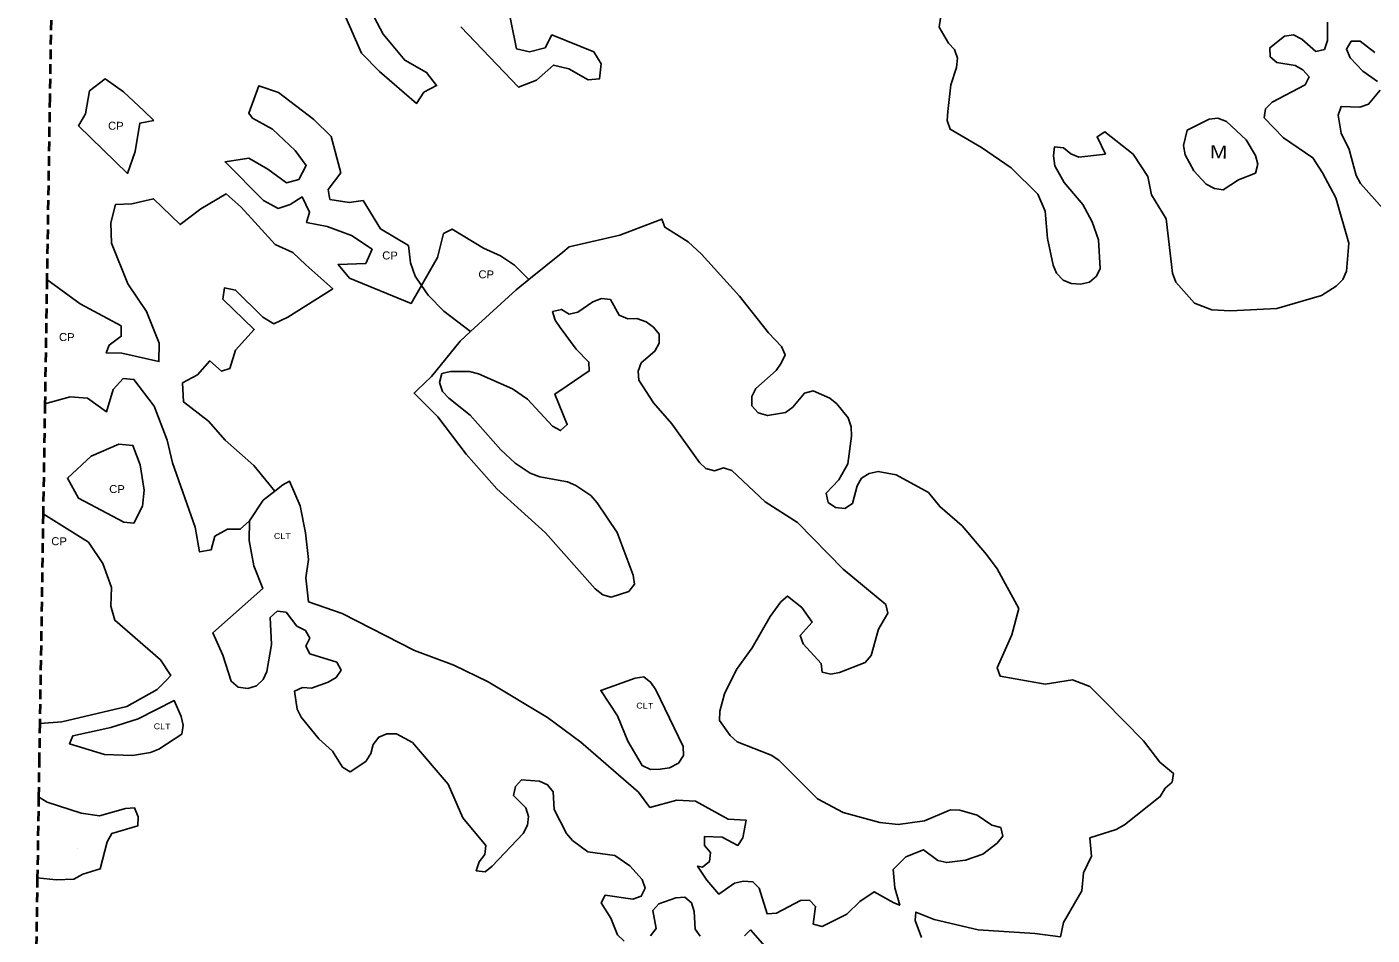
# Model space of a CAD drawing. Extents: x 713589 to 726391, y 7177764 to 7191819.
# Drawn here: x 713596 to 714671, y 7178865 to 7179591 of the extents above; entities that cross this region are included whole.
import ezdxf
from ezdxf.enums import TextEntityAlignment as Align

# ---------------------------------------------------------------- set-up
doc = ezdxf.new("R2010")
doc.units = 0
doc.header["$LTSCALE"] = 2.6
doc.linetypes.add('MEDIUM_DASHED', pattern=[4.5, 3, -1.5])
doc.layers.add('63', color=7, linetype='Continuous', lineweight=25)

msp = doc.modelspace()

# ---------------------------------------------------------------- linework, layer by layer
at = {"layer": '63', "linetype": 'MEDIUM_DASHED', "lineweight": 40}
for p, q in [((713608.65, 7179201.34), (713605.98, 7179033.91)), ((713605.04, 7178975.31), (713604, 7178910.37))]:
    msp.add_line(p, q, dxfattribs=at)
for points in [[(713619.62, 7179888.54), (713613.97, 7179534.19), (713611.65, 7179388.89)], [(713611.65, 7179388.89), (713610.06, 7179289.38), (713608.65, 7179201.34)], [(713605.98, 7179033.91), (713605.54, 7179006.32), (713605.04, 7178975.31)], [(713604, 7178910.37), (713599.18, 7178608.3), (713595.68, 7178388.53)]]:
    msp.add_lwpolyline(points, dxfattribs=at)
at = {"layer": '63'}
for points in [[(713942.56, 7179590.82), (713988.88, 7179542.69), (714003.14, 7179548.3), (714016.75, 7179560.21), (714029, 7179557.21), (714044.57, 7179548.56), (714053.52, 7179549.21), (714054.86, 7179561.14), (714048.91, 7179570.76), (714015.46, 7179584.41), (714010.14, 7179574.14), (713997.54, 7179570.85), (713987.27, 7179573.18), (713978.73, 7179615.62)], [(713848.79, 7179602.58), (713863.32, 7179569.74), (713877.55, 7179555.14), (713907.34, 7179529.57), (713912.98, 7179538.51), (713923.26, 7179543.79), (713915.33, 7179554.41), (713897.78, 7179564.05), (713880.58, 7179584.96), (713871, 7179603.2)], [(714635.66, 7179594.6), (714635.64, 7179579.8), (714633.31, 7179572.73), (714626.34, 7179570.98), (714615.2, 7179580.83), (714608.58, 7179584.37), (714601.29, 7179583.39), (714589.67, 7179574.13), (714589.77, 7179566.95), (714595.29, 7179562.41), (714609.75, 7179559.96), (714615.93, 7179556.41), (714621.01, 7179550.88), (714617.79, 7179544.48), (714591.48, 7179530.49), (714586.17, 7179525.2), (714584.94, 7179518.13), (714600.6, 7179502.2), (714624.1, 7179486.14), (714631.82, 7179474.08), (714642.39, 7179454.18), (714652.82, 7179417.82), (714650.8, 7179395.51), (714647.91, 7179388.88), (714642.71, 7179383.59), (714630.88, 7179375.99), (714595.29, 7179365.66), (714558.17, 7179363.74), (714543.15, 7179364.53), (714529.24, 7179369.86), (714514.35, 7179386.79), (714511.71, 7179393.75), (714506.59, 7179437.39), (714495.02, 7179456.53), (714492.07, 7179471.11), (714480.28, 7179489.03), (714457.66, 7179506.74), (714451.47, 7179502.88), (714458.18, 7179489.06), (714436.86, 7179486.67), (714430.34, 7179489.33), (714424.5, 7179493.98), (714417.54, 7179494.99), (714416.53, 7179487.59), (714417.62, 7179479.74), (714425.22, 7179466.36), (714440.11, 7179448.77), (714447.49, 7179434.95), (714452.54, 7179420.47), (714454.05, 7179397.71), (714450.95, 7179391.42), (714445.31, 7179386.79), (714438.12, 7179385.14), (714430.83, 7179385.6), (714424.21, 7179388.15), (714419.14, 7179393.9), (714416.28, 7179400.32), (714411.78, 7179421.64), (714409.94, 7179443.52), (714404, 7179457.12), (714382.71, 7179478.03), (714358.99, 7179494.31), (714333.93, 7179508.93), (714331.63, 7179515.9), (714332.08, 7179523.08), (714334.44, 7179544.51), (714339.1, 7179558.31), (714339.88, 7179565.71), (714337.46, 7179572.56), (714332.61, 7179577.87), (714325.12, 7179590.59), (714326.13, 7179597.77)], [(714675.68, 7179547.08), (714664.1, 7179555.49), (714653.84, 7179566.11), (714650.87, 7179572.97), (714654.75, 7179579.26), (714661.93, 7179579.25), (714673.51, 7179570.39)], [(714691.07, 7179433.05), (714662.18, 7179465.68), (714658.77, 7179471.98), (714653.17, 7179492.76), (714646.56, 7179505.81), (714644.15, 7179520.17), (714646.71, 7179527.13), (714661.62, 7179526.66), (714668.58, 7179529.08), (714677.77, 7179540.11)], [(713611.65, 7179388.89), (713638.29, 7179369.28), (713671.07, 7179351.66), (713671.06, 7179343.38), (713661.43, 7179336.43), (713659.1, 7179330.14), (713671.7, 7179329.79), (713701.18, 7179323.11), (713701.54, 7179338.02), (713691.31, 7179363.23), (713676.43, 7179385.46), (713663.23, 7179417.96), (713662.92, 7179434.2), (713666.59, 7179448.77), (713679.52, 7179449.42), (713696.97, 7179453.36), (713718.18, 7179432.7), (713734.86, 7179445.35), (713755.09, 7179457.24), (713767.01, 7179446.62), (713794.13, 7179416.75), (713808.37, 7179410.43), (713818.63, 7179400.47), (713840.21, 7179381.35), (713804.31, 7179358.73), (713793.03, 7179353.45), (713784.42, 7179358.77), (713762.59, 7179380.34), (713753.64, 7179382.02), (713752.3, 7179373.07), (713777.45, 7179348.83), (713762.51, 7179332.29), (713757.84, 7179317.71), (713751.21, 7179315.41), (713741.95, 7179323.71), (713731.99, 7179312.45), (713720.04, 7179306.18), (713721.01, 7179290.93), (713740.87, 7179275.65), (713754.1, 7179260.39), (713777.27, 7179240.13), (713794.05, 7179219.61)], [(713997.05, 7179388.81), (714024.12, 7179410.76), (714029.18, 7179414.86), (714069.88, 7179424.24), (714103.3, 7179437.07), (714105.9, 7179430.55), (714124.55, 7179418.81), (714135.25, 7179408.96), (714165.58, 7179375.54), (714188.62, 7179346.23), (714199.09, 7179335.28), (714201.95, 7179328.53), (714198.74, 7179321.91), (714194.86, 7179316.06), (714178.49, 7179301.73), (714175.28, 7179295.33), (714175.48, 7179287.81), (714180.56, 7179282.17), (714187.95, 7179280.06), (714202.21, 7179282.47), (714208.07, 7179286.65), (714217.48, 7179297.8), (714224.44, 7179299.77), (714237.69, 7179293.9), (714243.32, 7179289.36), (714252.36, 7179278.08), (714254.77, 7179271.11), (714255.2, 7179263.6), (714252.18, 7179241.51), (714244.87, 7179228.71), (714234.8, 7179217.9), (714236.45, 7179210.6), (714242.41, 7179206.62), (714249.69, 7179205.72), (714255.78, 7179209.8), (714259.67, 7179223.71), (714263.1, 7179229.89), (714269.29, 7179233.64), (714276.48, 7179235.39), (714290.83, 7179232.72), (714316.55, 7179218.43), (714325.59, 7179207.25), (714343.57, 7179191.98), (714363.09, 7179168.86), (714371.57, 7179157.46), (714388.76, 7179125.84), (714383.2, 7179104.75), (714371.66, 7179078.26), (714373.97, 7179071.62), (714409.98, 7179065.38), (714431.74, 7179068.77), (714445.65, 7179063.44), (714457.24, 7179052.04), (714488.45, 7179019.85), (714501.56, 7179003.03), (714512.48, 7178993.96), (714511.48, 7178987), (714505.84, 7178982.04), (714501.96, 7178975.41), (714473.31, 7178952.81), (714466.68, 7178949.07), (714445.68, 7178942.37), (714446.98, 7178927.78), (714440.55, 7178914.31), (714439.2, 7178900.07), (714424.68, 7178874.79), (714422.19, 7178863.19), (714401.58, 7178865.9), (714356.38, 7178868.76), (714321.07, 7178876.98), (714306.62, 7178883.02), (714306.04, 7178876.31), (714311.1, 7178862.72)], [(713997.05, 7179388.81), (713985.66, 7179400.19), (713974.41, 7179407.83), (713960.83, 7179413.82), (713935.67, 7179429.11), (713928.7, 7179425.47), (713924.03, 7179406.26), (713911.25, 7179384.07)], [(713911.25, 7179384.07), (713916.54, 7179376.32), (713929.14, 7179363.52), (713950.4, 7179347.17)], [(713997.05, 7179388.81), (713986.95, 7179380.63), (713950.4, 7179347.17)], [(714212.01, 7179194.41), (714186.07, 7179210.91), (714159.49, 7179236.03), (714152.76, 7179238.14), (714145.57, 7179235.83), (714138.72, 7179237.61), (714133.65, 7179242.59), (714111.28, 7179273.45), (714096.72, 7179290.26), (714084.93, 7179308.4), (714084.39, 7179315.58), (714086.94, 7179322.1), (714097.79, 7179331.58), (714101.22, 7179337.87), (714101.34, 7179345.05), (714096.82, 7179350.69), (714090.86, 7179355.01), (714083.36, 7179357.56), (714076.29, 7179357.35), (714069.22, 7179360.24), (714062.28, 7179372.84), (714055.21, 7179373.74), (714048.25, 7179370.99), (714036.3, 7179362.61), (714029.23, 7179360.97), (714023.16, 7179364.84), (714016.09, 7179363.2), (714018.07, 7179356.24), (714022.14, 7179350.37), (714034.82, 7179333.12), (714045.08, 7179322.72), (714045.4, 7179315.65), (714027.82, 7179303.84), (714017.93, 7179297.2), (714027.76, 7179272.81), (714022.45, 7179267.96), (714016.05, 7179271.62), (713995.87, 7179293.19), (713984.06, 7179301.5), (713956.79, 7179313.25), (713949.73, 7179315.36), (713934.37, 7179315.17), (713927.52, 7179313.52), (713925.63, 7179306.35), (713928.05, 7179299.27), (713933.01, 7179293.96), (713950.11, 7179280.23), (713974.7, 7179252.69), (713986.17, 7179242.06), (713998.2, 7179233.98), (714005.93, 7179231.09), (714027.9, 7179226.97), (714034.64, 7179223.97), (714046.67, 7179216), (714051.63, 7179210.36), (714067.72, 7179186.47), (714080.48, 7179152.42), (714081.46, 7179145.24), (714076.92, 7179139.39), (714062.99, 7179134.89), (714056.15, 7179136.78), (714050.19, 7179141.54), (714010.38, 7179186.23), (713971.45, 7179221.54), (713946.97, 7179249.09), (713924.37, 7179279.06), (713905.32, 7179298.03), (713907.9, 7179300.47), (713919.23, 7179311.15), (713942.15, 7179339.61), (713950.4, 7179347.17)], [(713773.55, 7179195.73), (713766.25, 7179189.11), (713755.97, 7179189.13), (713746.02, 7179183.51), (713743.02, 7179172.58), (713733.74, 7179170.94), (713730.13, 7179190.83), (713711.98, 7179242.23), (713707.71, 7179260.46), (713697.48, 7179287.66), (713681.27, 7179308.89), (713672.66, 7179309.57), (713664.69, 7179300.97), (713659.36, 7179283.08), (713644.13, 7179294.04), (713630.21, 7179295.06), (713610.06, 7179289.38)], [(713794.05, 7179219.61), (713800.44, 7179224.52), (713805.7, 7179227.47), (713814.11, 7179207.88), (713818.5, 7179186.33), (713820.78, 7179164.9), (713818.66, 7179150.32), (713820.91, 7179131.06), (713847.66, 7179121.7), (713905.61, 7179092.11), (713937.08, 7179080.46), (713964.56, 7179067.16), (714011.91, 7179038.58), (714038.72, 7179018.98), (714084.72, 7178978.8), (714093.88, 7178966.67), (714115.42, 7178972.41), (714130.22, 7178971.61), (714156.38, 7178957.21), (714170.85, 7178956.41), (714168.28, 7178942.27), (714164.08, 7178936.31), (714151.6, 7178942.96), (714137.46, 7178943.43), (714137.45, 7178936.14), (714142.3, 7178930.61), (714141.52, 7178923.43), (714135.99, 7178918.91), (714132.02, 7178919.84), (714139.28, 7178908.45), (714148.95, 7178897.49), (714161.59, 7178906.05), (714168.67, 7178907.7), (714176.29, 7178907.35), (714181.25, 7178902.26), (714187.51, 7178881.7), (714195.03, 7178882.24), (714214.38, 7178892.26), (714221.45, 7178892.69), (714226.41, 7178887.6), (714224.51, 7178873.47), (714231.58, 7178871.47), (714251.26, 7178881.27), (714261.77, 7178891.41), (714273.15, 7178899.29), (714289.02, 7178890.38), (714293.64, 7178888.45), (714289.85, 7178902.41), (714288.32, 7178917), (714298.5, 7178927.25), (714312.54, 7178932.86), (714324.24, 7178924.34), (714331.19, 7178922.56), (714346.11, 7178924.63), (714360.04, 7178929.36), (714371.54, 7178938.18), (714376.08, 7178943.7), (714374.44, 7178950.66), (714367.37, 7178952.66), (714355.67, 7178960.52), (714341.76, 7178964.63), (714334.25, 7178964.87), (714313.57, 7178955.95), (714292.36, 7178953.11), (714277.67, 7178954.69), (714248.41, 7178962.58), (714227.99, 7178973.66), (714196.89, 7179004.53), (714190.71, 7179008.52), (714163.77, 7179019.06), (714158.03, 7179024.26), (714149.55, 7179036.2), (714149.78, 7179043.61), (714153.56, 7179057.63), (714163.09, 7179077.06), (714175.72, 7179094.27), (714190.12, 7179119.32), (714198.53, 7179131.02), (714203.84, 7179135.65), (714215.32, 7179126.68), (714223.69, 7179114.96), (714213.96, 7179104.26), (714216.48, 7179097.63), (714230.71, 7179081.8), (714231.69, 7179074.84), (714238.54, 7179073.29), (714245.61, 7179074.6), (714266.06, 7179082.63), (714270.71, 7179088.15), (714276.6, 7179109.35), (714284.02, 7179121.93), (714282.49, 7179128.89), (714248.4, 7179157.12), (714212.01, 7179194.41)], [(713794.05, 7179219.61), (713784.51, 7179212.28), (713773.55, 7179195.73)], [(713605.98, 7179033.91), (713623.49, 7179035.24), (713675.54, 7179047.42), (713699.75, 7179060.97), (713706.65, 7179068), (713710.77, 7179072.2), (713702.44, 7179084.82), (713666.04, 7179116.37), (713662.74, 7179127.64), (713663.43, 7179142.55), (713656.5, 7179161.79), (713644.93, 7179178.71), (713608.65, 7179201.34)], [(713818.37, 7179108.23), (713811.63, 7179111.55), (713802.92, 7179122.95), (713795.74, 7179123.51), (713790.21, 7179118.66), (713791.28, 7179096.89), (713787.6, 7179075.47), (713784.72, 7179069.07), (713779.3, 7179063.99), (713772.22, 7179061.91), (713764.71, 7179062.8), (713759.09, 7179067.56), (713752.38, 7179088.34), (713744.35, 7179106.28), (713784.26, 7179141.72), (713777.14, 7179159.93), (713773.52, 7179180.15), (713773.55, 7179195.73)], [(714073.25, 7178859.69), (714068.07, 7178864.78), (714062.68, 7178878.26), (714054.85, 7178890.32), (714058.18, 7178896.61), (714080.16, 7178893.48), (714087.01, 7178895.79), (714090, 7178902.19), (714087.58, 7178909.04), (714077.77, 7178920.11), (714065.74, 7178928.3), (714044.21, 7178931.1), (714031.96, 7178940.29), (714027.11, 7178945.82), (714017.2, 7178965.06), (714016.56, 7178979.31), (714012.04, 7178984.73), (714005.52, 7178987.73), (713991.17, 7178988.74), (713986.41, 7178983.34), (713984.74, 7178976.38), (713994.77, 7178966.31), (713996.86, 7178959.46), (713995.97, 7178952.5), (713992.64, 7178945.88), (713967.63, 7178919.85), (713962.21, 7178915.11), (713955.03, 7178916.11), (713957.25, 7178923.18), (713961.79, 7178929.14), (713962.8, 7178936.21), (713944.16, 7178958.44), (713932.5, 7178985.31), (713904.05, 7179018.49), (713891.25, 7179025.59), (713883.52, 7179025.49), (713876.99, 7179022.85), (713872.46, 7179017), (713870.68, 7179009.93), (713866.58, 7179003.53), (713854.08, 7178995.27), (713848.01, 7178999.03), (713840.08, 7179011.64), (713829.16, 7179021.49), (713814.94, 7179038.75), (713811.74, 7179045.38), (713809.56, 7179059.64), (713816.19, 7179062.5), (713823.26, 7179062.04), (713836.64, 7179066.99), (713843.05, 7179070.63), (713846.93, 7179076.48), (713843.4, 7179082.89), (713821.98, 7179089.44), (713818.79, 7179095.74), (713821.89, 7179102.04), (713818.37, 7179108.23)], [(713605.04, 7178975.31), (713611.88, 7178971.03), (713639.04, 7178962.04), (713653.62, 7178960.02), (713674.51, 7178965.95), (713681.8, 7178966.27), (713684.77, 7178959.31), (713684.43, 7178952.02), (713663.54, 7178945.76), (713659.88, 7178939.13), (713654.21, 7178917.6), (713640.28, 7178913.32), (713633.32, 7178909.35), (713619.07, 7178908.71), (713604, 7178910.37)], [(714134.02, 7178863.67), (714129.94, 7178869.43), (714129.3, 7178883.57), (714127.21, 7178890.42), (714121.7, 7178894.96), (714114.63, 7178894.53), (714100.92, 7178889.58), (714096.16, 7178884.29), (714098.79, 7178869.81), (714094.25, 7178864.18)], [(714193.2, 7178847.38), (714174.26, 7178868.83), (714169.59, 7178864.17)]]:
    msp.add_lwpolyline(points, dxfattribs=at)
for points in [[(713697.19, 7179516), (713685.92, 7179513.7), (713682.24, 7179491.17), (713676.16, 7179473.62), (713637, 7179511.76), (713642.52, 7179521.39), (713645.86, 7179539.61), (713658.14, 7179549.21), (713673.04, 7179538.91), (713689.25, 7179523.64)], [(713911.25, 7179384.07), (713906.11, 7179391.59), (713902.51, 7179402.01), (713900.89, 7179415.91), (713878.33, 7179429.2), (713864.45, 7179452.09), (713853.51, 7179450.45), (713837.94, 7179452.8), (713836.63, 7179460.75), (713846.59, 7179473.99), (713839.02, 7179503.17), (713825.12, 7179516.78), (713796.98, 7179538.37), (713781.09, 7179543.7), (713773.1, 7179521.84), (713776.07, 7179517.86), (713791.96, 7179508.88), (713810.16, 7179491.95), (713819.09, 7179480), (713813.11, 7179468.75), (713803.16, 7179466.11), (713788.27, 7179477.07), (713773.04, 7179485.72), (713754.14, 7179482.76), (713784.91, 7179451.89), (713796.5, 7179445.58), (713806.12, 7179448.87), (713815.74, 7179454.82), (713821.68, 7179442.55), (713819.35, 7179434.27), (713835.91, 7179431.26), (713855.12, 7179423.94), (713871.68, 7179412.97), (713866.69, 7179401.71), (713844.48, 7179400.76), (713853.75, 7179389.88), (713902.94, 7179369.65)], [(714578.02, 7179473.84), (714580.13, 7179480.91), (714578.26, 7179487.98), (714570.77, 7179500.48), (714554.89, 7179515.2), (714548.15, 7179517.75), (714541.19, 7179516.88), (714523.39, 7179508.07), (714520.61, 7179495.92), (714521.81, 7179488.52), (714528.75, 7179475.58), (714538.78, 7179464.96), (714545.41, 7179461.63), (714552.36, 7179460.41), (714564.64, 7179468.45)], [(713689.41, 7179220.39), (713686.13, 7179240.61), (713680.52, 7179256.2), (713669.26, 7179257.21), (713647.04, 7179247.64), (713628.06, 7179230), (713637.04, 7179213.85), (713673.13, 7179194.9), (713681.08, 7179193.89), (713688.06, 7179207.47)], [(714116.68, 7179002.12), (714109.5, 7178998.49), (714101.98, 7178997.18), (714094.36, 7178997.08), (714087.63, 7179000.29), (714076.28, 7179019.64), (714068.03, 7179039.99), (714054.53, 7179060.23), (714082.11, 7179070.12), (714089.07, 7179071.21), (714094.69, 7179066.56), (714098.55, 7179060.7), (714120.46, 7179015.37), (714120.67, 7179008.19)], [(713657.8, 7179009.07), (713629.86, 7179017.51), (713632.41, 7179024.03), (713662.92, 7179030.6), (713684.69, 7179037.53), (713713.55, 7179052.12), (713719.05, 7179039.46), (713720.58, 7179032.39), (713719.47, 7179025.32), (713701.11, 7179013.31), (713694.59, 7179010.56), (713680, 7179008.26)]]:
    msp.add_lwpolyline(points, close=True, dxfattribs=at)

# ---------------------------------------------------------------- texts
for s, height, width, p in [('CP', 6.4, 1.05, (713666.76, 7179508.51)), ('M', 10.4, 1.2, (714548.6, 7179485.6)), ('CP', 6.4, 1.05, (713885.99, 7179404.8)), ('CP', 6.4, 1.05, (713962.94, 7179389.7)), ('CP', 6.4, 1.05, (713627.54, 7179339.56)), ('CP', 6.4, 1.05, (713667.66, 7179218.05)), ('CP', 6.4, 1.05, (713621.36, 7179176.32)), ('CLT', 4.64, 1.15, (713799.88, 7179181.32)), ('CLT', 4.64, 1.15, (714089.68, 7179045.73)), ('CLT', 4.64, 1.15, (713703.77, 7179029.18)), ('CP', 0.32, 1.05, (713636.18, 7178933.99))]:
    msp.add_text(s, height=height, rotation=359.062, dxfattribs=dict(at, width=width)).set_placement(p, align=Align.CENTER)

doc.saveas('drawing.dxf')
